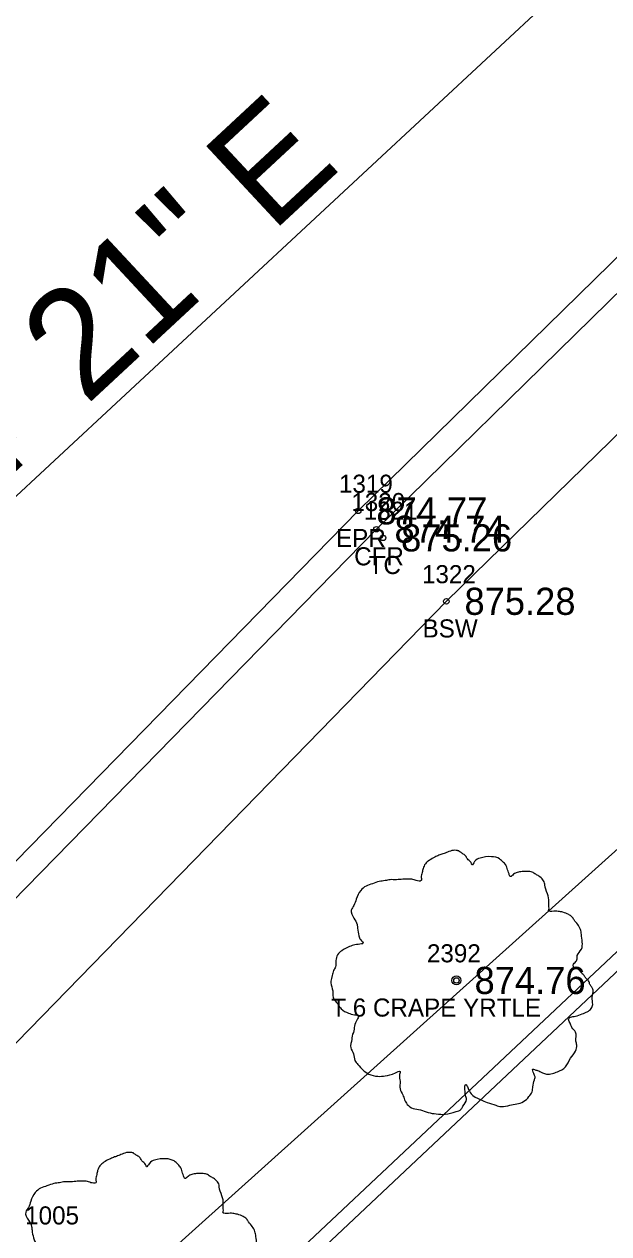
# Model space of a CAD drawing. Extents: x 1622501 to 1626664, y 1117816 to 1121579.
# Drawn here: x 1623774.2 to 1623806.5, y 1119016.9 to 1119083.8 of the extents above; entities that cross this region are included whole.
import ezdxf

# ---------------------------------------------------------------- set-up
doc = ezdxf.new("R2010")
doc.units = 0
for name, color, linetype in [('RD_EX_Conc', 7, 'Continuous'), ('RD_EX_Conc_txCode', 7, 'Continuous'), ('RD_EX_DV_Prop_txCode', 7, 'Continuous'), ('RD_EX_Road', 7, 'Continuous'), ('RD_EX_Road_txCode', 7, 'Continuous'), ('RD_EX_TX_Conc_ELEV', 7, 'Continuous'), ('RD_EX_TX_Road_ELEV', 7, 'Continuous'), ('RD_EX_TX_VEG_ELEV', 7, 'Continuous'), ('RD_EX_VEG', 7, 'Continuous'), ('RD_EX_VEG_txCode', 7, 'Continuous'), ('RD_HC_Cl', 7, 'Continuous'), ('RD_HC_Data', 7, 'Continuous'), ('RD_SMD_Locator', 7, 'Continuous')]:
    doc.layers.add(name, color=color, linetype=linetype)

msp = doc.modelspace()

# ---------------------------------------------------------------- linework, layer by layer
at = {"layer": 'RD_EX_Conc'}
for points in [[(1623723.663, 1118851.276), (1623685.686, 1118891.781), (1623680.278, 1118899.276), (1623678.543, 1118902.667), (1623678.543, 1118902.667), (1623675.573, 1118911.952), (1623675.054, 1118920.354), (1623676.566, 1118930.331), (1623679.225, 1118937.184), (1623684.435, 1118944.641), (1623689.976, 1118950.418), (1623724.501, 1118984.8), (1623759.009, 1119020.42), (1623793.698, 1119055.906), (1623829.35, 1119090.862), (1623865.612, 1119125.129), (1623901.916, 1119159.181), (1623933.224, 1119188.498)], [(1623676.299, 1118912.014), (1623681.213, 1118913.011), (1623680.576, 1118920.41), (1623681.86, 1118928.773), (1623684.243, 1118934.734), (1623688.548, 1118940.788), (1623694.147, 1118946.67), (1623728.265, 1118980.628), (1623762.622, 1119016.068), (1623797.565, 1119051.919), (1623833.104, 1119086.631), (1623869.148, 1119120.8), (1623905.547, 1119154.999), (1623936.969, 1119184.346), (1623933.79, 1119188.026)], [(1623776.374, 1119003.735), (1623808.841, 1119034.289), (1623817.882, 1119024.564), (1623821.612, 1119022.069), (1623824.094, 1119022.765), (1623826.626, 1119024.788), (1623826.626, 1119024.788), (1623825.953, 1119029.369), (1623815.684, 1119040.66), (1623840.6, 1119064.039), (1623868.084, 1119089.909)]]:
    msp.add_lwpolyline(points, dxfattribs=at)
at = {"layer": 'RD_EX_Road'}
for points in [[(1623722.97, 1118850.612), (1623684.945, 1118891.225), (1623679.413, 1118898.675), (1623674.261, 1118911.526), (1623673.503, 1118920.185), (1623675.206, 1118930.826), (1623677.985, 1118937.822), (1623683.61, 1118945.518), (1623688.806, 1118951.265), (1623723.469, 1118985.717), (1623758.003, 1119021.43), (1623792.693, 1119056.92), (1623828.408, 1119091.915), (1623864.599, 1119126.191), (1623900.882, 1119160.216), (1623932.37, 1119189.416), (1623932.628, 1119189.219), (1623935.818, 1119192.17), (1623973.771, 1119227.767), (1623990.875, 1119243.538), (1624009.987, 1119262.018), (1624046.295, 1119296.153)], [(1623776.805, 1119003.039), (1623808.744, 1119033.096), (1623817.315, 1119023.967), (1623821.371, 1119021.115), (1623825.354, 1119021.212), (1623827.704, 1119023.202), (1623826.634, 1119029.88), (1623816.804, 1119040.763), (1623841.225, 1119063.389), (1623868.182, 1119088.58)]]:
    msp.add_lwpolyline(points, dxfattribs=at)
at = {"layer": 'RD_EX_VEG'}
msp.add_lwpolyline([(1623719.641, 1118895.843), (1623705.963, 1118915.58), (1623701.704, 1118941.089), (1623733.735, 1118974.045), (1623762.596, 1118998.968), (1623764.149, 1118997.606), (1623773.667, 1119008.214), (1623809.616, 1119040.562), (1623866.904, 1119093.207), (1623868.266, 1119096.09), (1623881.794, 1119107.882), (1623919.645, 1119143.849), (1623945.126, 1119165.729), (1623961.583, 1119122.835), (1623970.119, 1119088.038)], dxfattribs=at)
for centre, radius in [((1623798.121, 1119030.957), 0.25), ((1623798.108, 1119030.938), 0.0001)]:
    msp.add_circle(centre, radius, dxfattribs=at)
for points in [[(1623798.253, 1119038.124), (1623797.953, 1119038.149), (1623797.628, 1119038.049), (1623797.378, 1119037.949), (1623797.153, 1119037.874), (1623796.929, 1119037.774), (1623796.629, 1119037.599), (1623796.404, 1119037.399), (1623796.279, 1119037.149), (1623796.229, 1119036.924), (1623796.179, 1119036.649), (1623796.179, 1119036.474), (1623796.054, 1119036.449), (1623795.904, 1119036.474), (1623795.654, 1119036.549), (1623795.404, 1119036.549), (1623795.154, 1119036.549), (1623794.804, 1119036.524), (1623794.455, 1119036.524), (1623794.18, 1119036.474), (1623793.855, 1119036.425), (1623793.48, 1119036.3), (1623793.13, 1119036.175), (1623792.83, 1119035.925), (1623792.58, 1119035.45), (1623792.455, 1119035.1), (1623792.306, 1119034.85), (1623792.455, 1119034.4), (1623792.63, 1119034.051), (1623792.655, 1119033.851), (1623792.73, 1119033.426), (1623792.83, 1119033.201), (1623792.955, 1119033.001), (1623792.88, 1119032.976), (1623792.505, 1119032.926), (1623792.206, 1119032.826), (1623791.781, 1119032.601), (1623791.556, 1119032.376), (1623791.456, 1119032.051), (1623791.431, 1119031.702), (1623791.331, 1119031.502), (1623791.256, 1119031.227), (1623791.231, 1119031.152), (1623791.181, 1119030.827), (1623791.281, 1119030.377), (1623791.306, 1119030.027), (1623791.431, 1119029.802), (1623791.581, 1119029.628), (1623791.756, 1119029.378), (1623792.156, 1119029.153), (1623792.48, 1119029.053), (1623792.68, 1119029.028), (1623792.505, 1119028.528), (1623792.455, 1119028.178), (1623792.331, 1119027.778), (1623792.331, 1119027.703), (1623792.281, 1119027.229), (1623792.43, 1119026.904), (1623792.505, 1119026.529), (1623792.68, 1119026.304), (1623792.955, 1119026.004), (1623793.28, 1119025.779), (1623793.78, 1119025.654), (1623794.18, 1119025.679), (1623794.755, 1119025.854), (1623795.004, 1119025.929), (1623794.979, 1119025.754), (1623795.004, 1119025.379), (1623795.004, 1119024.955), (1623795.154, 1119024.63), (1623795.254, 1119024.355), (1623795.404, 1119024.105), (1623795.729, 1119023.88), (1623796.129, 1119023.805), (1623796.554, 1119023.655), (1623797.004, 1119023.58), (1623797.503, 1119023.555), (1623798.103, 1119023.705), (1623798.378, 1119023.83), (1623798.478, 1119024.005), (1623798.678, 1119024.38), (1623798.628, 1119024.605), (1623798.653, 1119025.204), (1623798.753, 1119025.029), (1623798.928, 1119024.68), (1623799.427, 1119024.38), (1623799.827, 1119024.205), (1623800.302, 1119024.055), (1623800.602, 1119023.98), (1623801.077, 1119024.055), (1623801.452, 1119024.13), (1623801.826, 1119024.255), (1623802.126, 1119024.53), (1623802.301, 1119024.805), (1623802.351, 1119025.079), (1623802.426, 1119025.454), (1623802.476, 1119025.629)], [(1623802.476, 1119025.629), (1623802.401, 1119025.804), (1623802.351, 1119026.054), (1623802.426, 1119026.029), (1623802.601, 1119025.979), (1623802.876, 1119025.854), (1623803.101, 1119025.779), (1623803.426, 1119025.804), (1623803.701, 1119025.904), (1623804.15, 1119026.179), (1623804.425, 1119026.654), (1623804.7, 1119027.054), (1623804.775, 1119027.378), (1623804.725, 1119027.603), (1623804.7, 1119028.103), (1623804.5, 1119028.353), (1623804.45, 1119028.478), (1623804.35, 1119028.878), (1623804.425, 1119028.928), (1623804.7, 1119028.978), (1623805.075, 1119029.103), (1623805.35, 1119029.228), (1623805.575, 1119029.403), (1623805.65, 1119029.628), (1623805.625, 1119030.027), (1623805.675, 1119030.427), (1623805.6, 1119030.577), (1623805.5, 1119030.727), (1623805.425, 1119030.927), (1623805.275, 1119031.077), (1623805.175, 1119031.227), (1623805.075, 1119031.327), (1623804.95, 1119031.477), (1623804.775, 1119031.602), (1623804.625, 1119031.652), (1623804.575, 1119031.802), (1623804.725, 1119032.001), (1623804.775, 1119032.101), (1623804.8, 1119032.326), (1623805.025, 1119032.676), (1623805.075, 1119033.076), (1623805.025, 1119033.501), (1623804.975, 1119033.776), (1623804.825, 1119034.051), (1623804.625, 1119034.3), (1623804.5, 1119034.475), (1623804.325, 1119034.6), (1623804, 1119034.725), (1623803.751, 1119034.775), (1623803.401, 1119034.775), (1623803.201, 1119034.825), (1623803.226, 1119034.875), (1623803.226, 1119035.025), (1623803.226, 1119035.3), (1623803.151, 1119035.75), (1623803.001, 1119036.25), (1623803.001, 1119036.275), (1623802.901, 1119036.524), (1623802.676, 1119036.724), (1623802.501, 1119036.824), (1623802.301, 1119036.949), (1623802.051, 1119036.974), (1623801.751, 1119036.974), (1623801.477, 1119036.924), (1623801.277, 1119036.824), (1623801.102, 1119036.699), (1623801.027, 1119036.849), (1623800.927, 1119037.149), (1623800.877, 1119037.299), (1623800.727, 1119037.474), (1623800.502, 1119037.674), (1623800.052, 1119037.799), (1623799.427, 1119037.724), (1623799.128, 1119037.524), (1623798.978, 1119037.349), (1623798.928, 1119037.474), (1623798.728, 1119037.674), (1623798.628, 1119037.849), (1623798.453, 1119037.974), (1623798.303, 1119038.074), (1623798.203, 1119038.124)], [(1623780.265, 1119021.424), (1623779.965, 1119021.449), (1623779.641, 1119021.349), (1623779.391, 1119021.249), (1623779.166, 1119021.174), (1623778.941, 1119021.074), (1623778.641, 1119020.899), (1623778.416, 1119020.699), (1623778.291, 1119020.449), (1623778.241, 1119020.224), (1623778.191, 1119019.949), (1623778.191, 1119019.774), (1623778.066, 1119019.749), (1623777.916, 1119019.774), (1623777.666, 1119019.849), (1623777.417, 1119019.849), (1623777.167, 1119019.849), (1623776.817, 1119019.824), (1623776.467, 1119019.824), (1623776.192, 1119019.774), (1623775.867, 1119019.724), (1623775.492, 1119019.599), (1623775.143, 1119019.474), (1623774.843, 1119019.224), (1623774.593, 1119018.75), (1623774.468, 1119018.4), (1623774.318, 1119018.15), (1623774.468, 1119017.7), (1623774.643, 1119017.35), (1623774.668, 1119017.15), (1623774.743, 1119016.726), (1623774.843, 1119016.501), (1623774.968, 1119016.301), (1623774.893, 1119016.276), (1623774.518, 1119016.226), (1623774.218, 1119016.126), (1623773.793, 1119015.901), (1623773.568, 1119015.676), (1623773.468, 1119015.351), (1623773.443, 1119015.001), (1623773.343, 1119014.801), (1623773.268, 1119014.527), (1623773.243, 1119014.452), (1623773.193, 1119014.127), (1623773.293, 1119013.677), (1623773.318, 1119013.327), (1623773.443, 1119013.102), (1623773.593, 1119012.927), (1623773.768, 1119012.677), (1623774.168, 1119012.452), (1623774.493, 1119012.352), (1623774.693, 1119012.328), (1623774.518, 1119011.828), (1623774.468, 1119011.478), (1623774.343, 1119011.078), (1623774.343, 1119011.003), (1623774.293, 1119010.528), (1623774.443, 1119010.203), (1623774.518, 1119009.829), (1623774.693, 1119009.604), (1623774.968, 1119009.304), (1623775.292, 1119009.079), (1623775.792, 1119008.954), (1623776.192, 1119008.979), (1623776.767, 1119009.154), (1623777.017, 1119009.229), (1623776.992, 1119009.054), (1623777.017, 1119008.679), (1623777.017, 1119008.254), (1623777.167, 1119007.929), (1623777.267, 1119007.655), (1623777.417, 1119007.405), (1623777.741, 1119007.18), (1623778.141, 1119007.105), (1623778.566, 1119006.955), (1623779.016, 1119006.88), (1623779.516, 1119006.855), (1623780.115, 1119007.005), (1623780.39, 1119007.13), (1623780.49, 1119007.305), (1623780.69, 1119007.68), (1623780.64, 1119007.904), (1623780.665, 1119008.504), (1623780.765, 1119008.329), (1623780.94, 1119007.979), (1623781.44, 1119007.68), (1623781.84, 1119007.505), (1623782.314, 1119007.355), (1623782.614, 1119007.28), (1623783.089, 1119007.355), (1623783.464, 1119007.43), (1623783.839, 1119007.555), (1623784.139, 1119007.829), (1623784.314, 1119008.104), (1623784.364, 1119008.379), (1623784.438, 1119008.754), (1623784.488, 1119008.929)], [(1623784.488, 1119008.929), (1623784.414, 1119009.104), (1623784.364, 1119009.354), (1623784.438, 1119009.329), (1623784.613, 1119009.279), (1623784.888, 1119009.154), (1623785.113, 1119009.079), (1623785.438, 1119009.104), (1623785.713, 1119009.204), (1623786.163, 1119009.479), (1623786.438, 1119009.954), (1623786.712, 1119010.353), (1623786.787, 1119010.678), (1623786.737, 1119010.903), (1623786.712, 1119011.403), (1623786.513, 1119011.653), (1623786.463, 1119011.778), (1623786.363, 1119012.178), (1623786.438, 1119012.228), (1623786.712, 1119012.278), (1623787.087, 1119012.402), (1623787.362, 1119012.527), (1623787.587, 1119012.702), (1623787.662, 1119012.927), (1623787.637, 1119013.327), (1623787.687, 1119013.727), (1623787.612, 1119013.877), (1623787.512, 1119014.027), (1623787.437, 1119014.227), (1623787.287, 1119014.377), (1623787.187, 1119014.527), (1623787.087, 1119014.626), (1623786.962, 1119014.776), (1623786.787, 1119014.901), (1623786.638, 1119014.951), (1623786.588, 1119015.101), (1623786.737, 1119015.301), (1623786.787, 1119015.401), (1623786.812, 1119015.626), (1623787.037, 1119015.976), (1623787.087, 1119016.376), (1623787.037, 1119016.801), (1623786.987, 1119017.075), (1623786.837, 1119017.35), (1623786.638, 1119017.6), (1623786.513, 1119017.775), (1623786.338, 1119017.9), (1623786.013, 1119018.025), (1623785.763, 1119018.075), (1623785.413, 1119018.075), (1623785.213, 1119018.125), (1623785.238, 1119018.175), (1623785.238, 1119018.325), (1623785.238, 1119018.6), (1623785.163, 1119019.05), (1623785.013, 1119019.549), (1623785.013, 1119019.574), (1623784.913, 1119019.824), (1623784.688, 1119020.024), (1623784.513, 1119020.124), (1623784.314, 1119020.249), (1623784.064, 1119020.274), (1623783.764, 1119020.274), (1623783.489, 1119020.224), (1623783.289, 1119020.124), (1623783.114, 1119019.999), (1623783.039, 1119020.149), (1623782.939, 1119020.449), (1623782.889, 1119020.599), (1623782.739, 1119020.774), (1623782.514, 1119020.974), (1623782.064, 1119021.099), (1623781.44, 1119021.024), (1623781.14, 1119020.824), (1623780.99, 1119020.649), (1623780.94, 1119020.774), (1623780.74, 1119020.974), (1623780.64, 1119021.149), (1623780.465, 1119021.274), (1623780.315, 1119021.374), (1623780.215, 1119021.424)]]:
    msp.add_spline(points, degree=3, dxfattribs=at)
at = {"layer": 'RD_HC_Cl'}
msp.add_line((1623608.837, 1118904.32), (1623937.248, 1119209.793), dxfattribs=at)
at = {"layer": 'RD_SMD_Locator'}
for centre in [(1623792.693, 1119056.92), (1623793.698, 1119055.906), (1623794.064, 1119055.426), (1623797.565, 1119051.919), (1623798.121, 1119030.957)]:
    msp.add_circle(centre, 0.15, dxfattribs=at)

# ---------------------------------------------------------------- texts
at = {"layer": 'RD_EX_Conc_txCode'}
for s, p in [('1320', (1623792.312, 1119056.906)), ('1321', (1623793.001, 1119056.426)), ('CFR', (1623792.469, 1119053.906)), ('TC', (1623793.269, 1119053.426)), ('1322', (1623796.218, 1119052.919)), ('BSW', (1623796.25, 1119049.919))]:
    msp.add_text(s, height=1, dxfattribs=at).set_placement(p)
at = {"layer": 'RD_EX_DV_Prop_txCode'}
msp.add_text('1005', height=1, dxfattribs=at).set_placement((1623774.287, 1119017.464))
at = {"layer": 'RD_EX_Road_txCode'}
for s, p in [('1319', (1623791.63, 1119057.92)), ('EPR', (1623791.465, 1119054.92))]:
    msp.add_text(s, height=1, dxfattribs=at).set_placement(p)
at = {"layer": 'RD_EX_TX_Conc_ELEV'}
for s, p in [('874.74', (1623794.698, 1119055.156)), ('875.26', (1623795.064, 1119054.676)), ('875.28', (1623798.565, 1119051.169))]:
    msp.add_text(s, height=1.5, dxfattribs=at).set_placement(p)
at = {"layer": 'RD_EX_TX_Road_ELEV'}
msp.add_text('874.77', height=1.5, dxfattribs=at).set_placement((1623793.693, 1119056.17))
at = {"layer": 'RD_EX_TX_VEG_ELEV'}
msp.add_text('874.76', height=1.5, dxfattribs=at).set_placement((1623799.121, 1119030.207))
at = {"layer": 'RD_EX_VEG_txCode'}
for s, p in [('2392', (1623796.491, 1119031.957)), ('T 6 CRAPE YRTLE', (1623791.204, 1119028.957))]:
    msp.add_text(s, height=1, dxfattribs=at).set_placement(p)
at = {"layer": 'RD_HC_Data'}
msp.add_text('N 47%%d 04\' 21" E', height=6, rotation=42.92763, dxfattribs=at).set_placement((1623751.969, 1119038.82))

doc.saveas('drawing.dxf')
